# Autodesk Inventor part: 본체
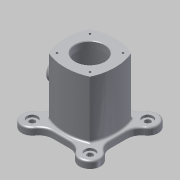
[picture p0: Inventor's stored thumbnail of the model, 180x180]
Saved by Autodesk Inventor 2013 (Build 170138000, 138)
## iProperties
Created: 2016-05
Part Number: 본체
Material: 알루미늄 6061
Document SubType Name: Modeling
Designer: dgall
Mass: 1129.59 g
Surface Area: 852.47 cm^2
Volume: 416.823 cm^3
Density: 2.71 g/cm^3
Author: dgall
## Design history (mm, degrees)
sketch "스케치1"
  geometry: L1 (-14.162, -49)-(14.162, -49); L2 (14.162, 49)-(-14.162, 49); L3 (-49, 14.162)-(-49, -14.162); L4 (49, 14.162)-(49, -14.162); L5 (49.497, 49.497)-(-49.497, -49.497); L6 (-49.497, 49.497)-(49.497, -49.497); L7 (0, 0)-(0, 49); A1 r 18 centre (-49.497, 49.497) between (-34.706, 59.754) and (-59.754, 34.706); A2 r 25 centre (-14.162, 74) between (-34.706, 59.754) and (-14.162, 49); A3 r 25 centre (-74, 14.162) between (-49, 14.162) and (-59.754, 34.706); A4 r 25 centre (-74, -14.162) between (-59.754, -34.706) and (-49, -14.162); A5 r 18 centre (-49.497, -49.497) between (-59.754, -34.706) and (-34.706, -59.754); A6 r 25 centre (-14.162, -74) between (-14.162, -49) and (-34.706, -59.754); A7 r 25 centre (14.162, -74) between (34.706, -59.754) and (14.162, -49); A8 r 18 centre (49.497, -49.497) between (34.706, -59.754) and (59.754, -34.706); A9 r 25 centre (74, -14.162) between (49, -14.162) and (59.754, -34.706); A10 r 25 centre (74, 14.162) between (59.754, 34.706) and (49, 14.162); A11 r 18 centre (49.497, 49.497) between (59.754, 34.706) and (34.706, 59.754); A12 r 25 centre (14.162, 74) between (14.162, 49) and (34.706, 59.754); 1 further point
  constraints: 24 point on circle, 14 end point, 12 centre point, 6 tangent, 3 midpoint, 2 parallel, 1 equal radius, 1 horizontal, 1 perpendicular, 41 other
  dimensions: "d29" = 18 radius of A1; "d30" = 25 radius of A2; "d33" = 360 deg dimension on point (0, 0) A2.centre (derived); "d35" = 98 distance between parallel lines of L3 L4; "d40" = 49 distance of L7.start L7.end; "d41" = 140.00001 distance of L6.start L6.end
extrude "돌출1" new body sketch "스케치1" distance "d42" = 12; taper "d43" = 0 deg
sketch "스케치2"
  geometry: C1 r 25 at (0, 0); 1 further point
  constraints: 1 centre point, 1 coincident
  dimensions: "d44" = 50 diameter of C1
extrude "돌출2" cut sketch "스케치2" distance "d46" = 12; taper "d47" = 0 deg
sketch "스케치3"
  geometry: L1 (-49, 14.162)-(-49, -14.162) reference; L2 (-49, 14.162)-(-49, -14.162) reference; L3 (-14.162, -49)-(14.162, -49) reference; L4 (49, -14.162)-(49, 14.162) reference; L5 (14.162, 49)-(-14.162, 49) reference; L6 (0, 0)-(-35.355, 35.355); L7 (0, 0)-(35.355, -35.355); L8 (0, 0)-(35.355, 35.355); L9 (0, 0)-(-35.355, -35.355); L10 (0, 0)-(0, -43); L11 (0, 0)-(0, 43); L12 (0, 0)-(-43, 0); L13 (0, 0)-(43, 0); C1 r 25 at (0, 0) reference; C2 r 25 at (0, 0) reference; A1 r 18 centre (-49.497, 49.497) between (-34.706, 59.754) and (-59.754, 34.706) reference; A2 r 25 centre (-74, 14.162) between (-49, 14.162) and (-59.754, 34.706) reference; A3 r 25 centre (-74, -14.162) between (-59.754, -34.706) and (-49, -14.162) reference; A4 r 18 centre (-49.497, -49.497) between (-59.754, -34.706) and (-34.706, -59.754) reference; A5 r 25 centre (-14.162, -74) between (-14.162, -49) and (-34.706, -59.754) reference; A6 r 25 centre (14.162, -74) between (34.706, -59.754) and (14.162, -49) reference; A7 r 18 centre (49.497, -49.497) between (34.706, -59.754) and (59.754, -34.706) reference; A8 r 25 centre (74, -14.162) between (49, -14.162) and (59.754, -34.706) reference; A9 r 25 centre (74, 14.162) between (59.754, 34.706) and (49, 14.162) reference; A10 r 18 centre (49.497, 49.497) between (59.754, 34.706) and (34.706, 59.754) reference; A11 r 25 centre (14.162, 74) between (14.162, 49) and (34.706, 59.754) reference; A12 r 25 centre (-14.162, 74) between (-34.706, 59.754) and (-14.162, 49) reference; A13 r 85.579 centre (0, -42.579) between (35.355, 35.355) and (-35.355, 35.355); A14 r 85.579 centre (42.579, 0) between (-35.355, 35.355) and (-35.355, -35.355); A15 r 85.579 centre (0, 42.579) between (-35.355, -35.355) and (35.355, -35.355); A16 r 85.579 centre (-42.579, 0) between (35.355, -35.355) and (35.355, 35.355)
  constraints: 16 end point, 12 point on circle, 4 centre point, 3 collinear, 3 perpendicular, 1 parallel, 1 vertical alignment
  dimensions: "d52" = 45 deg angle of L11 L6; "d53" = 45 deg angle of L10 L9; "d55" = 50 distance of L6.start L6.end; "d56" = 50 distance of L6.start L7.end; "d57" = 50 distance of L6.start L9.end; "d58" = 50 distance of L6.start L8.end; "d61" = 43 distance of L10.start L11.end; "d62" = 43 distance of L10.start L12.end; "d63" = 43 distance of L10.start L10.end; "d64" = 43 distance of L10.start L13.end
extrude "돌출3" join sketch "스케치3" distance "d65" = 98; taper "d66" = 0 deg
sketch "스케치4"
  geometry: C1 r 25 at (0, 0); A1 r 85.579 centre (-42.579, 0) between (35.355, -35.355) and (35.355, 35.355) reference; A2 r 85.579 centre (0, -42.579) between (35.355, 35.355) and (-35.355, 35.355) reference; A3 r 85.579 centre (42.579, 0) between (-35.355, 35.355) and (-35.355, -35.355) reference; A4 r 85.579 centre (0, 42.579) between (-35.355, -35.355) and (35.355, -35.355) reference; 1 further point
  constraints: 1 centre point, 1 coincident
  dimensions: "d67" = 50 diameter of C1
extrude "돌출4" cut sketch "스케치4" distance "d69" = 12; taper "d70" = 0 deg
sketch "스케치5"
  geometry: C1 r 25 at (0, 0) reference; C2 r 35 at (0, 0)
  constraints: 1 centre point, 1 coincident
  dimensions: "d71" = 70 diameter of C2
extrude "돌출5" cut sketch "스케치5" distance "d73" = 86; taper "d74" = 0 deg
node "작업축2"
node "작업 평면1"
node "작업 평면2"
sketch "스케치6"
  geometry: L1 (86, -35.355)-(86, 35.355) reference; L2 (86, -35.355)-(-12, -35.355) reference; L3 (-12, 35.355)-(-12, -35.355) reference; L4 (86, 35.355)-(-12, 35.355) reference; C1 r 20 at (37, 0); 2 further points
  constraints: 1 centre point, 1 horizontal alignment, 1 midpoint
  dimensions: "d77" = 40 diameter of C1; "d79" = 49 distance from line of L3 C1.centre
extrude "돌출6" join sketch "스케치6" stored distance "d80" = 86; taper "d81" = 10 deg
sketch "스케치7"
  geometry: C1 r 20 at (0, 0) reference; C2 r 15 at (0, 0); 1 further point
  constraints: 1 centre point, 1 coincident
  dimensions: "d82" = 30 diameter of C2
extrude "돌출7" cut sketch "스케치7" distance "d84" = 8; taper "d85" = 0 deg
sketch "스케치8"
  geometry: C1 r 15 at (0, 0) reference; C2 r 12.5 at (0, 0); 1 further point
  constraints: 1 centre point, 1 coincident
  dimensions: "d86" = 25 diameter of C2
extrude "돌출8" cut sketch "스케치8" stored distance "d88" = 8; taper "d89" = 0 deg
node "작업 평면3"
sketch "스케치9"
  geometry: 1 further point
node "작업 평면5"
  node "작업 평면4"
sketch "스케치10"
  geometry: L1 (35.355, 12)-(-35.355, 12) reference; C1 r 20 at (0, -37) reference; 2 further points
  constraints: 1 other
  dimensions: "d93" = 49 distance from line of L1 point (-29, -37); "d94" = 29 distance of C1.centre point (-29, -37)
feature "엠보싱1" sketch "스케치10" dims "d29" = 18, "d30" = 25, "d33" = 360 deg (derived), "d35" = 98, "d40" = 49, "d41" = 140.00001, "d95" = 0.5, "d96" = 0
fillet "모깎기1" dims "d97" = 3
fillet "모깎기2" dims "d98" = 3
fillet "모깎기3" dims "d99" = 3
fillet "모깎기4" dims "d100" = 3
chamfer "모따기1" distance "d101" = 1; stored, may be unused: second distance "d102" = 2, angle "d103" = 45 deg
chamfer "모따기2" distance "d104" = 1; stored, may be unused: second distance "d105" = 2, angle "d106" = 45 deg
fillet "모깎기5" dims "d107" = 3
sketch "스케치11"
  geometry: L1 (-46, 0)-(-46, 14.162) reference; L2 (-14.162, 46)-(0, 46) reference; C1 r 9 at (-49.497, 49.497); A1 r 88.579 centre (42.579, 0) between (-37.616, 37.616) and (-46, 0) reference; A2 r 88.579 centre (0, -42.579) between (0, 46) and (-37.616, 37.616) reference; A3 r 28 centre (-14.162, 74) between (-37.171, 58.045) and (-14.162, 46) reference; A4 r 15 centre (-49.497, 49.497) between (-37.171, 58.045) and (-58.045, 37.171) reference; A5 r 28 centre (-74, 14.162) between (-46, 14.162) and (-58.045, 37.171) reference; 1 further point
  constraints: 1 centre point, 1 coincident
  dimensions: "d109" = 18 diameter of C1
extrude "돌출9" cut sketch "스케치11" distance "d111" = 4; taper "d112" = 0 deg
sketch "스케치12"
  geometry: C1 r 9 at (0, 0) reference; C2 r 5 at (0, 0); 1 further point
  constraints: 1 centre point, 1 coincident
  dimensions: "d113" = 10 diameter of C2
extrude "돌출10" cut sketch "스케치12" distance "d115" = 10; taper "d116" = 0 deg
sketch "스케치13"
  geometry: L1 (0, 0)-(-28.284, -28.284); L2 (0, 0)-(0, -40); C1 r 26 at (0, 0) reference; A1 r 3 centre (-33.083, -33.083) between (-35.832, -34.285) and (-34.285, -35.832) reference; A2 r 85.579 centre (0, 42.579) between (-34.285, -35.832) and (34.285, -35.832) reference; A3 r 3 centre (33.083, -33.083) between (34.285, -35.832) and (35.832, -34.285) reference; A4 r 85.579 centre (-42.579, 0) between (35.832, -34.285) and (35.832, 34.285) reference; A5 r 3 centre (33.083, 33.083) between (35.832, 34.285) and (34.285, 35.832) reference; A6 r 85.579 centre (0, -42.579) between (34.285, 35.832) and (-34.285, 35.832) reference; A7 r 3 centre (-33.083, 33.083) between (-34.285, 35.832) and (-35.832, 34.285) reference; A8 r 85.579 centre (42.579, 0) between (-35.832, 34.285) and (-35.832, -34.285) reference; A9 r 40 centre (0, 0) between (-28.284, -28.284) and (0, -40)
  constraints: 4 end point, 2 point on circle, 1 centre point, 1 coincident, 1 vertical
  dimensions: "d120" = 80 diameter of A9; "d122" = 45 deg angle of L2 L1
hole "구멍1" sketch "스케치13" at (-28.284, -28.284) diameter "d124" = 3.242; stored, may be unused: countersink angle "d128" = 90 deg, drill point angle "d130" = 118 deg; dims "d125" = 7, "d126" = 4, "d127" = 2, "d129" = 10
node "작업 평면6"
node "솔리드1"
pattern_circular "원형 패턴1" dims angle "d118" = 360 deg
pattern_circular "원형 패턴2" dims angle "d132" = 360 deg
mirror "대칭1"
node "투영된 루프1"
node "투영된 루프2"
node "투영된 루프3"
node "투영된 루프4"
node "투영된 루프5"
node "투영된 루프6"
node "투영된 루프7"
node "투영된 루프8"
node "투영된 루프9"
other parameters: "d75" = 0, "d76" = -55, "d90" = -55, "d91" = 0, "d92" = 55
